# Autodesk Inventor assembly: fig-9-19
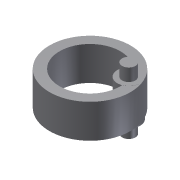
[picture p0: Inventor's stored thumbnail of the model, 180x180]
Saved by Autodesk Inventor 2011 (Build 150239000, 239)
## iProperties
Shininess: 64.0
Length Units: 11269
Angle Units: 11279
Time Units: 11290
Mass Units: 11283
Length Display Precision: 3
Angle Display Precision: 2
Created: 2002-01
Part Number: fig-9-19
Document SubType Name: Assembly
Designer: ***
Density: 0.0
Volumn: 0.0
Area: 0.0
PropertySet Name: Model Information
Control State: 0
Master: False
Checked Out: False
Author: ***
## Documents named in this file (3)
- C:\Users\CADSoft\Desktop\part files\c09-inv-2011-prt\fig-9-19.iam
- C:\Users\CADSoft\Desktop\inventor\c09-inv-2010-prt\c09\Part8.ipt
- C:\Users\CADSoft\Desktop\inventor\c09-inv-2010-prt\c09\Part9.ipt
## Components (2 placed, 2 different names)
1. Part8:1 — Flush:1
2. Part9:1 — Flush:1
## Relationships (1: Flush 1)
- Flush:1: Part8:1 ↔ Part9:1
